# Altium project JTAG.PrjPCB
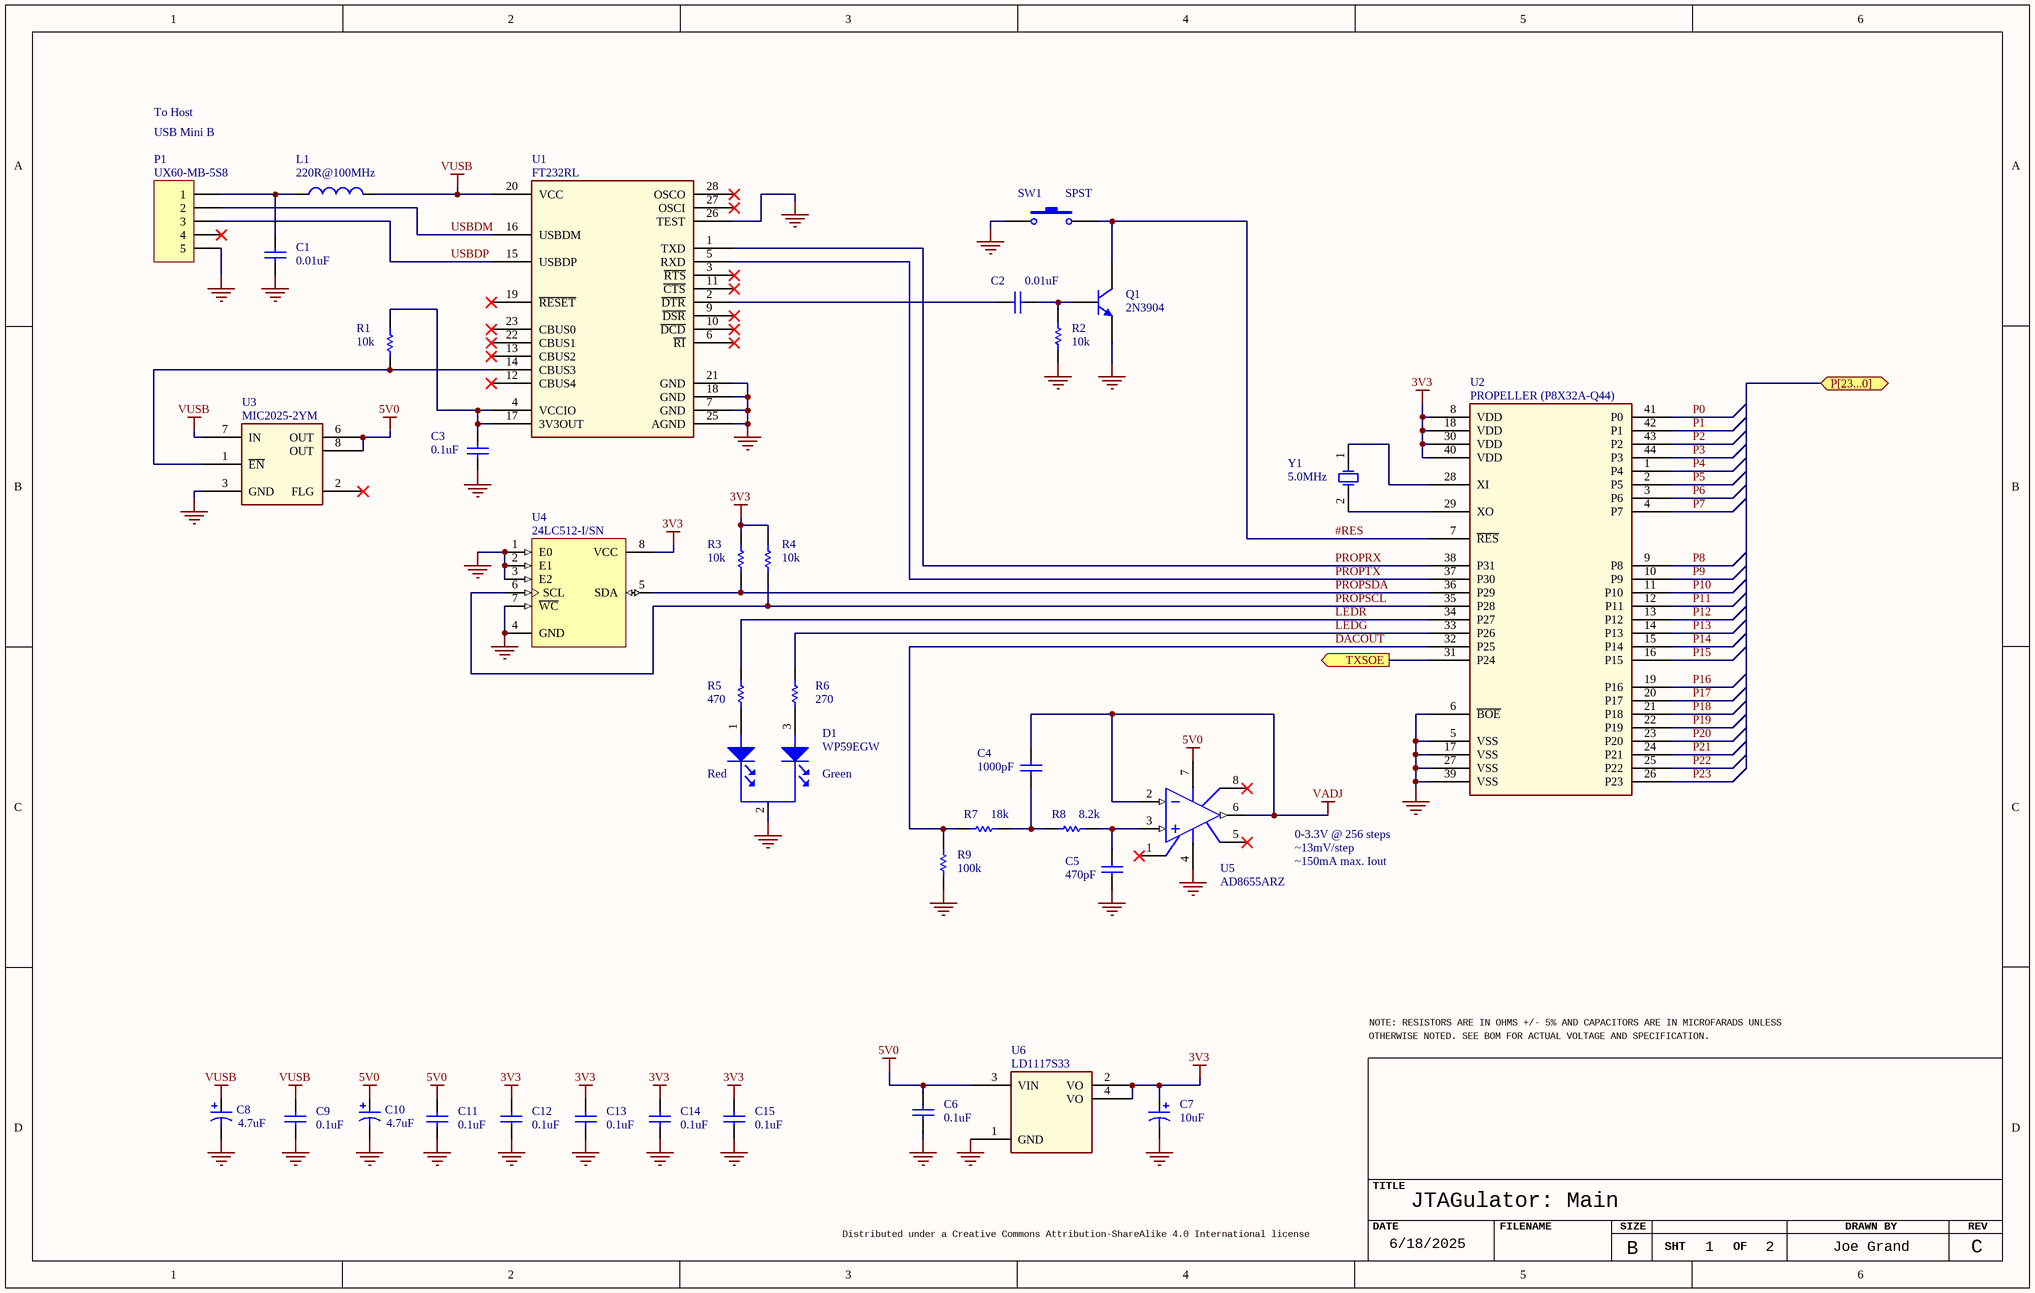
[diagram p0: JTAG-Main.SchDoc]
2 sheets, 65 parts. Net scope: global (net labels, ports and power ports of the same name join across sheets).
Board file: JTAG.PcbDoc
Sheets:
  JTAG-Main.SchDoc
  JTAG-Target.SchDoc

## Sheet JTAG-Main.SchDoc: JTAGulator: Main
size B; Engineer: Joe Grand; Revision: C; SheetNumber: 1; SheetTotal: 2; PageSetup: Record=PageOptions¦CenterHorizontal=True¦CenterVertical=True¦PrintScale=0.70¦XCorrection=1.00¦YCorrection=1.00¦PrintKind=0¦BorderSize=5000000¦LeftOffset=0¦BottomOffset=0¦Orientation=2¦PaperLength=1000¦PaperWidth=1000¦Scale=100¦PaperSource=7¦PrintQuality=-4¦MediaType=1¦DitherType=10¦PaperKind=Letter¦PrintScaleMode=1

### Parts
(Parts that share a designator on the sheet are numbered #1, #2 ... from top to bottom, then left to right.)
*#1  Schematic Modify Date: 6/18/2025  Page Size: B  RevCode: C  Page Count: 2  Page Number: 1  OrgName: Joe Grand  Title: JTAGulator: Main  (hidden comment: GIS Title Block)  (graphical)
C1  value 0.01uF  [C1206]  (hidden comment: Cap)
C2  value 0.01uF  [C1206]  (hidden comment: Cap)
C3  value 0.1uF  [C1206]  (hidden comment: Cap)
C4  value 1000pF  [C1206]  (hidden comment: Cap)
C5  value 470pF  [C1206]  (hidden comment: Cap)
C6  value 0.1uF  [C1206]  (hidden comment: Cap)
C7  value 10uF  [TC3216 (A)]  (hidden comment: Cap Pol1)
C8  value 4.7uF  [TC3216 (A)]  (hidden comment: Cap Pol1)
C9  value 0.1uF  [C1206]  (hidden comment: Cap)
C10  value 4.7uF  [TC3216 (A)]  (hidden comment: Cap Pol1)
C11  value 0.1uF  [C1206]  (hidden comment: Cap)
C12  value 0.1uF  [C1206]  (hidden comment: Cap)
C13  value 0.1uF  [C1206]  (hidden comment: Cap)
C14  value 0.1uF  [C1206]  (hidden comment: Cap)
C15  value 0.1uF  [C1206]  (hidden comment: Cap)
D1  WP59EGW  [WP59EGW]
L1  value 220R@100MHz  [C0805]  (hidden comment: Inductor)
P1  UX60-MB-5S8  [HRS UX60-MB-5S8 MINI-USB - NO SLOTS]
Q1  2N3904  [SOT23-3]
R1  value 10k  [C1206]  (hidden comment: Res1)
R2  value 10k  [C1206]  (hidden comment: Res1)
R3  value 10k  [C1206]  (hidden comment: Res1)
R4  value 10k  [C1206]  (hidden comment: Res1)
R5  value 470  [C1206]  (hidden comment: Res1)
R6  value 270  [C1206]  (hidden comment: Res1)
R7  value 18k  [C1206]  (hidden comment: Res1)
R8  value 8.2k  [C1206]  (hidden comment: Res1)
R9  value 100k  [C1206]  (hidden comment: Res1)
SW1  SPST  [C&K KSC SPST SWITCH]
U1  FT232RL  [SOP65P780-28BN]
U2  PROPELLER (P8X32A-Q44)  [TQFP80P1200X1200-44AN]
U3  MIC2025-2YM  [SOIC127P600-8BM]
U4  24LC512-I/SN  [SOIC127P600-8BM]
U5  AD8655ARZ  [R-8_N]
U6  LD1117S33  [SOT-223]
Y1  5.0MHz  [XTL_HC49-4H]

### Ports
P[23...0] (bidir), TXSOE (out)

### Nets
3V3: C7.1 C12.2 C13.2 C14.2 C15.2 R3.2 R4.2 U2.8(VDD) U2.18(VDD) U2.30(VDD) U2.40(VDD) U4.8(VCC) U6.2(VO) U6.4(VO)
5V0: C6.2 C10.1 C11.2 U3.6(OUT) U3.8(OUT) U5.7(V+) U6.3(VIN)
GND: C1.1 C3.1 C5.1 C6.1 C7.2 C8.2 C9.1 C10.2 C11.1 C12.1 C13.1 C14.1 C15.1 D1.2(CATHODE) P1.5 Q1.1(E) R2.1 R9.1 SW1.2 U1.7(GND) U1.18(GND) U1.21(GND) U1.25(AGND) U1.26(TEST) U2.5(VSS) U2.6(~{BOE}) U2.17(VSS) U2.27(VSS) U2.39(VSS) U3.3(GND) U4.1(E0) U4.2(E1) U4.3(E2) U4.4(GND) U4.7(~{WC}) U5.4(V-) U6.1(GND)
VADJ: C4.2 U5.2(IN-) U5.6(OUT)
VUSB: C8.1 C9.2 L1.2 U1.20(VCC) U3.7(IN)
#RES: Q1.3(C) SW1.1 U2.7(~{RES})
DACOUT: R7.2 R9.2 U2.32(P25)
LEDG: R6.2 U2.33(P26)
LEDR: R5.2 U2.34(P27)
P0: U2.41(P0)
P1: U2.42(P1)
P2: U2.43(P2)
P3: U2.44(P3)
P4: U2.1(P4)
P5: U2.2(P5)
P6: U2.3(P6)
P7: U2.4(P7)
P8: U2.9(P8)
P9: U2.10(P9)
P10: U2.11(P10)
P11: U2.12(P11)
P12: U2.13(P12)
P13: U2.14(P13)
P14: U2.15(P14)
P15: U2.16(P15)
P16: U2.19(P16)
P17: U2.20(P17)
P18: U2.21(P18)
P19: U2.22(P19)
P20: U2.23(P20)
P21: U2.24(P21)
P22: U2.25(P22)
P23: U2.26(P23)
PROPRX: U1.1(TXD) U2.38(P31)
PROPSCL: R4.1 U2.35(P28) U4.6(SCL)
PROPSDA: R3.1 U2.36(P29) U4.5(SDA)
PROPTX: U1.5(RXD) U2.37(P30)
USBDM: P1.2 U1.16(USBDM)
USBDP: P1.3 U1.15(USBDP)
NetC1_2: C1.2 L1.1 P1.1
NetC2_1: C2.1 Q1.2(B) R2.2
NetC2_2: C2.2 U1.2(~{DTR})
NetC3_2: C3.2 R1.2 U1.4(VCCIO) U1.17(3V3OUT)
NetC4_1: C4.1 R7.1 R8.2
NetC5_2: C5.2 R8.1 U5.3(IN+)
NetD1_1: D1.1(ARED) R5.1
NetD1_3: D1.3(AGREEN) R6.1
NetR1_1: R1.1 U1.14(CBUS3) U3.1(~{EN})
NetR10_2: U2.31(P24) ; port TXSOE
NetU2_28: U2.28(XI) Y1.1(OSC1)
NetU2_29: U2.29(XO) Y1.2(OSC2)

Not connected (* = marked no-connect by the designer): P1 4*; U1 3(~{RTS})* 6(~{RI})* 9(~{DSR})* 10(~{DCD})* 11(~{CTS})* 12(CBUS4)* 13(CBUS2)* 19(~{RESET})* 22(CBUS1)* 23(CBUS0)* 27(OSCI)* 28(OSCO)*; U3 2(FLG)*; U5 1(OS_NULL)* 5(OS_NULL)* 8(NC)*

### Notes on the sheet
- To Host
- USB Mini B
- (near D1) Red
- (near D1) Green
- 0-3.3V @ 256 steps
- 3mV/step
- 50mA max. Iout
- (near *#1) OTHERWISE NOTED. SEE BOM FOR ACTUAL VOLTAGE AND SPECIFICATION.
- (near *#1) NOTE: RESISTORS ARE IN OHMS +/- 5% AND CAPACITORS ARE IN MICROFARADS UNLESS
- Distributed under a Creative Commons Attribution-ShareAlike 4.0 International license

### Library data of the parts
C1-C6 C9 C11-C15 = Cap: Capacitor
C7 C8 C10 = Cap Pol1: Polarized Capacitor (Radial)
D1 = SSL-LX5097
L1 = Inductor: MPZ2012S221A
P1 = Header 5: Header, 5-Pin
Q1 = 2N3904: NPN General Purpose Amplifier
R1-R9 = Res1: Resistor
SW1 = SW-PB: Switch
U1 = FT232RL: USB UART Asynchronous Serial Data Transfer Chip
U2 = PROPELLER (ALT)
U3 = MIC2025-2: Single-Channel Power Distribution Switch
U4 = M24C02WDW6: 2Kbit Serial I²C Bus EEPROM
U5 = AD548AR: Low-Noise, Precision CMOS Op Amp; Note: Pin 8 is not connected.
U6 = LD1117: LD1117xx 800mA LDO Linear Regulator
Y1 = XTAL: Crystal Oscillator

## Sheet JTAG-Target.SchDoc: JTAGulator: Target Interface
size B; Engineer: Joe Grand; Revision: C; SheetNumber: 2; SheetTotal: 2; PageSetup: Record=PageOptions¦CenterHorizontal=True¦CenterVertical=True¦PrintScale=0.70¦XCorrection=1.00¦YCorrection=1.00¦PrintKind=0¦BorderSize=5000000¦LeftOffset=0¦BottomOffset=0¦Orientation=2¦PaperLength=1000¦PaperWidth=1000¦Scale=100¦PaperSource=7¦PrintQuality=-4¦MediaType=1¦DitherType=10¦PaperKind=Letter¦PrintScaleMode=1
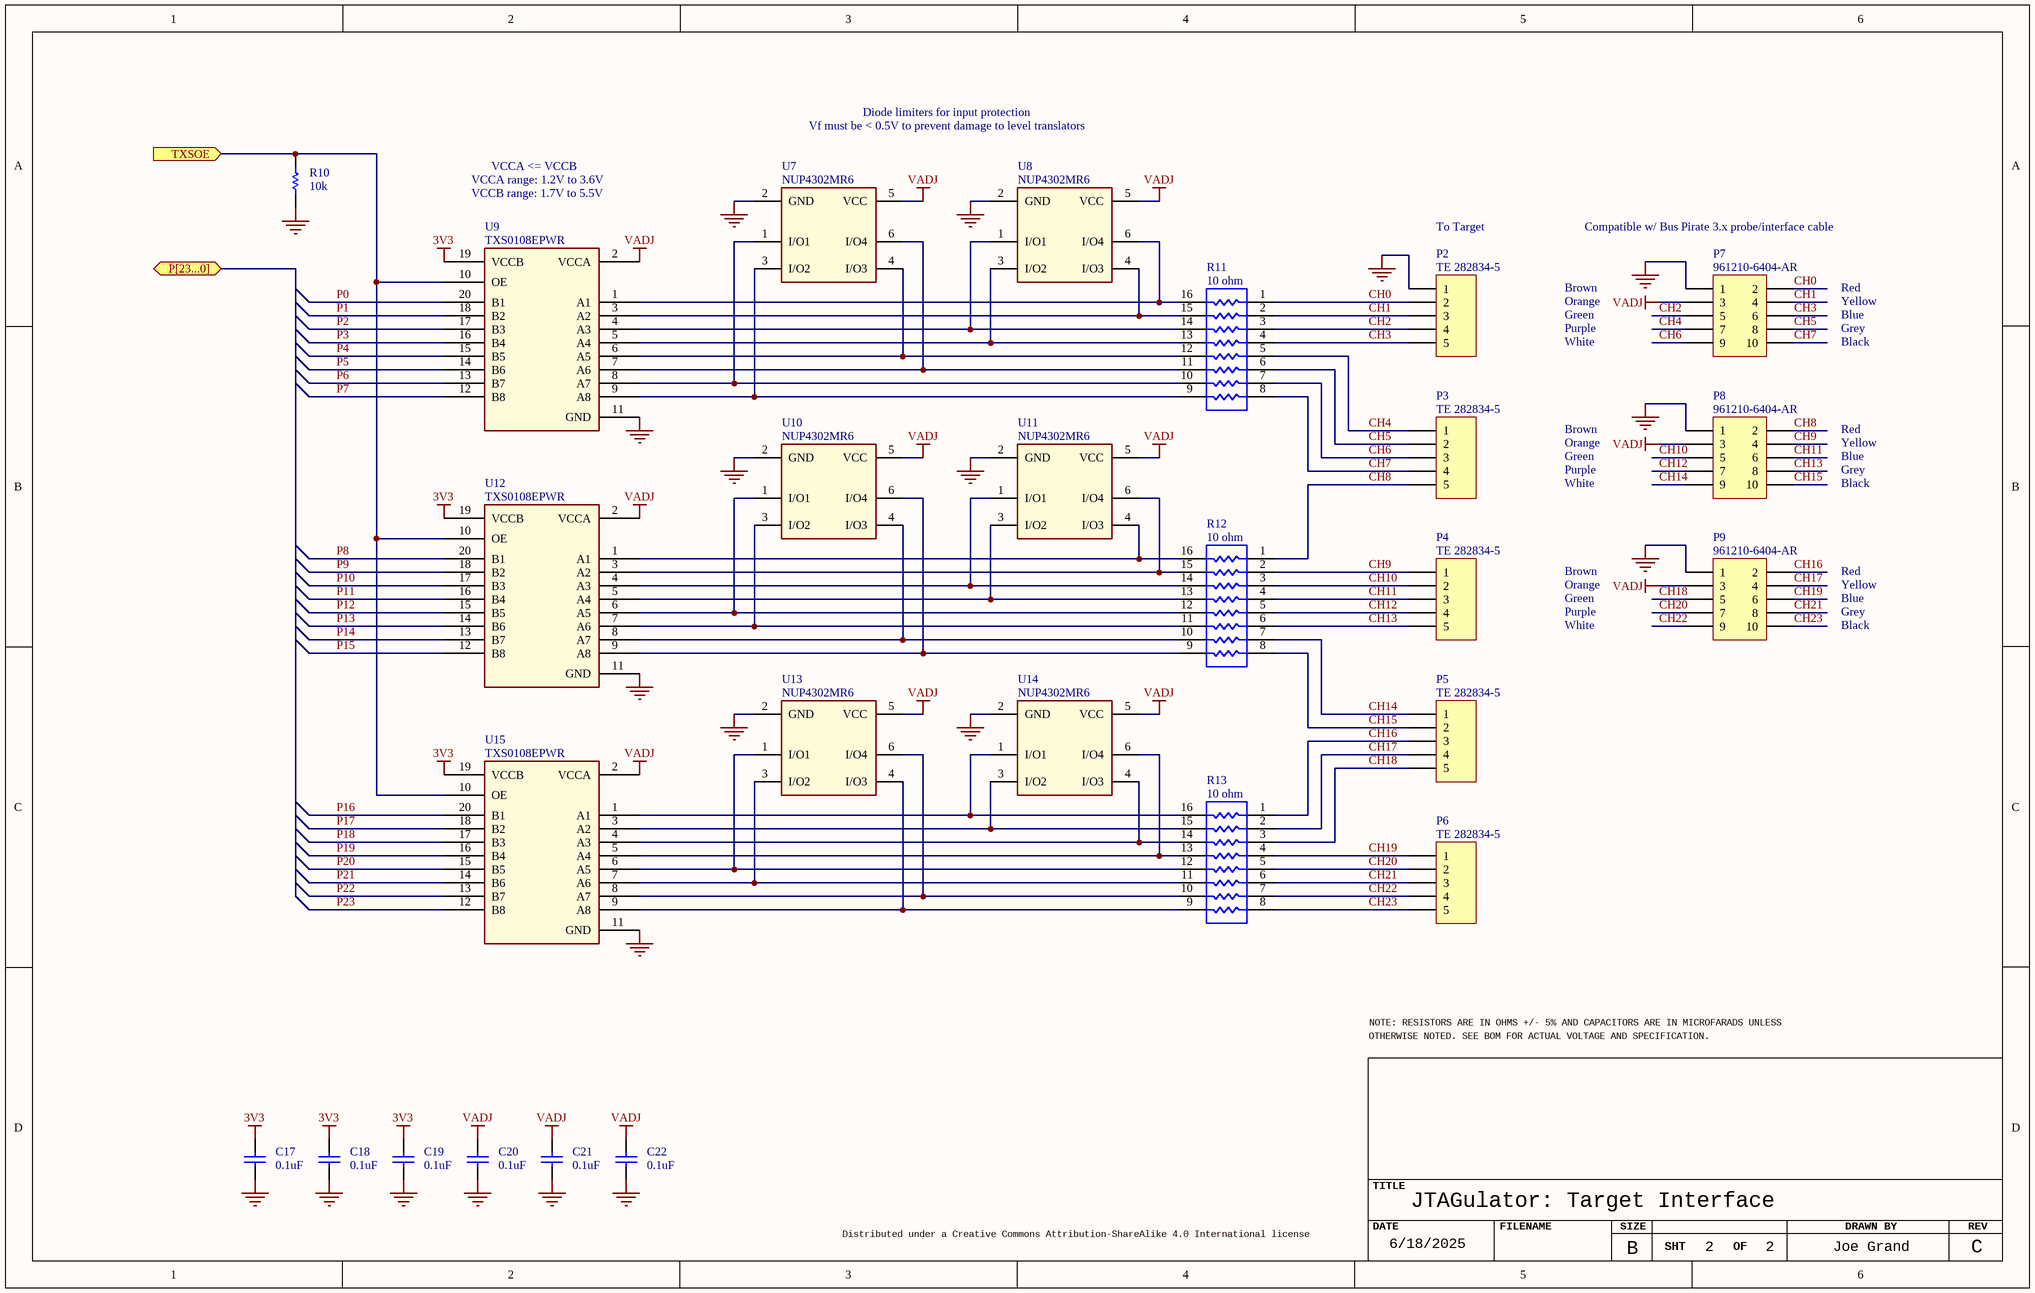
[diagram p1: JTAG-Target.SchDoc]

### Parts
(Parts that share a designator on the sheet are numbered #1, #2 ... from top to bottom, then left to right.)
*#2  Schematic Modify Date: 6/18/2025  Page Size: B  RevCode: C  Page Count: 2  OrgName: Joe Grand  Title: JTAGulator: Target Interface  (hidden comment: GIS Title Block)  (graphical)
C17  value 0.1uF  [C1206]  (hidden comment: Cap)
C18  value 0.1uF  [C1206]  (hidden comment: Cap)
C19  value 0.1uF  [C1206]  (hidden comment: Cap)
C20  value 0.1uF  [C1206]  (hidden comment: Cap)
C21  value 0.1uF  [C1206]  (hidden comment: Cap)
C22  value 0.1uF  [C1206]  (hidden comment: Cap)
P2  TE 282834-5  [TE282834-5]
P3  TE 282834-5  [TE282834-5]
P4  TE 282834-5  [TE282834-5]
P5  TE 282834-5  [TE282834-5]
P6  TE 282834-5  [TE282834-5]
P7  961210-6404-AR  [HDR2X5 - SHROUD]
P8  961210-6404-AR  [HDR2X5 - SHROUD]
P9  961210-6404-AR  [HDR2X5 - SHROUD]
R10  value 10k  [C1206]  (hidden comment: Res1)
R11  value 10 ohm  [SO-G16 - WIDE]  (hidden comment: 4816P-1-102LF)
R12  value 10 ohm  [SO-G16 - WIDE]  (hidden comment: 4816P-1-102LF)
R13  value 10 ohm  [SO-G16 - WIDE]  (hidden comment: 4816P-1-102LF)
U7  NUP4302MR6  [TSOP-6_M]
U8  NUP4302MR6  [TSOP-6_M]
U9  TXS0108EPWR  [SOP65P640-20AN]
U10  NUP4302MR6  [TSOP-6_M]
U11  NUP4302MR6  [TSOP-6_M]
U12  TXS0108EPWR  [SOP65P640-20AN]
U13  NUP4302MR6  [TSOP-6_M]
U14  NUP4302MR6  [TSOP-6_M]
U15  TXS0108EPWR  [SOP65P640-20AN]

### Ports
P[23...0] (bidir), TXSOE (in)

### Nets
3V3: C17.2 C18.2 C19.2 U9.19(VCCB) U12.19(VCCB) U15.19(VCCB)
GND: C17.1 C18.1 C19.1 C20.1 C21.1 C22.1 P2.1 P7.1 P8.1 P9.1 R10.1 U7.2(GND) U8.2(GND) U9.11(GND) U10.2(GND) U11.2(GND) U12.11(GND) U13.2(GND) U14.2(GND) U15.11(GND)
VADJ: C20.2 C21.2 C22.2 P7.3 P8.3 P9.3 U7.5(VCC) U8.5(VCC) U9.2(VCCA) U10.5(VCC) U11.5(VCC) U12.2(VCCA) U13.5(VCC) U14.5(VCC) U15.2(VCCA)
CH0: P2.2 P7.2 R11.1
CH1: P2.3 P7.4 R11.2
CH2: P2.4 P7.5 R11.3
CH3: P2.5 P7.6 R11.4
CH4: P3.1 P7.7 R11.5
CH5: P3.2 P7.8 R11.6
CH6: P3.3 P7.9 R11.7
CH7: P3.4 P7.10 R11.8
CH8: P3.5 P8.2 R12.1
CH9: P4.1 P8.4 R12.2
CH10: P4.2 P8.5 R12.3
CH11: P4.3 P8.6 R12.4
CH12: P4.4 P8.7 R12.5
CH13: P4.5 P8.8 R12.6
CH14: P5.1 P8.9 R12.7
CH15: P5.2 P8.10 R12.8
CH16: P5.3 P9.2 R13.1
CH17: P5.4 P9.4 R13.2
CH18: P5.5 P9.5 R13.3
CH19: P6.1 P9.6 R13.4
CH20: P6.2 P9.7 R13.5
CH21: P6.3 P9.8 R13.6
CH22: P6.4 P9.9 R13.7
CH23: P6.5 P9.10 R13.8
P0: U9.20(B1)
P1: U9.18(B2)
P2: U9.17(B3)
P3: U9.16(B4)
P4: U9.15(B5)
P5: U9.14(B6)
P6: U9.13(B7)
P7: U9.12(B8)
P8: U12.20(B1)
P9: U12.18(B2)
P10: U12.17(B3)
P11: U12.16(B4)
P12: U12.15(B5)
P13: U12.14(B6)
P14: U12.13(B7)
P15: U12.12(B8)
P16: U15.20(B1)
P17: U15.18(B2)
P18: U15.17(B3)
P19: U15.16(B4)
P20: U15.15(B5)
P21: U15.14(B6)
P22: U15.13(B7)
P23: U15.12(B8)
NetR10_2: R10.2 U9.10(OE) U12.10(OE) U15.10(OE) ; port TXSOE
NetR11_9: R11.9 U7.3(I/O2) U9.9(A8)
NetR11_10: R11.10 U7.1(I/O1) U9.8(A7)
NetR11_11: R11.11 U7.6(I/O4) U9.7(A6)
NetR11_12: R11.12 U7.4(I/O3) U9.6(A5)
NetR11_13: R11.13 U8.3(I/O2) U9.5(A4)
NetR11_14: R11.14 U8.1(I/O1) U9.4(A3)
NetR11_15: R11.15 U8.4(I/O3) U9.3(A2)
NetR11_16: R11.16 U8.6(I/O4) U9.1(A1)
NetR12_9: R12.9 U10.6(I/O4) U12.9(A8)
NetR12_10: R12.10 U10.4(I/O3) U12.8(A7)
NetR12_11: R12.11 U10.3(I/O2) U12.7(A6)
NetR12_12: R12.12 U10.1(I/O1) U12.6(A5)
NetR12_13: R12.13 U11.3(I/O2) U12.5(A4)
NetR12_14: R12.14 U11.1(I/O1) U12.4(A3)
NetR12_15: R12.15 U11.6(I/O4) U12.3(A2)
NetR12_16: R12.16 U11.4(I/O3) U12.1(A1)
NetR13_9: R13.9 U13.4(I/O3) U15.9(A8)
NetR13_10: R13.10 U13.6(I/O4) U15.8(A7)
NetR13_11: R13.11 U13.3(I/O2) U15.7(A6)
NetR13_12: R13.12 U13.1(I/O1) U15.6(A5)
NetR13_13: R13.13 U14.6(I/O4) U15.5(A4)
NetR13_14: R13.14 U14.4(I/O3) U15.4(A3)
NetR13_15: R13.15 U14.3(I/O2) U15.3(A2)
NetR13_16: R13.16 U14.1(I/O1) U15.1(A1)

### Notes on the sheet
- Vf must be < 0.5V to prevent damage to level translators
- Diode limiters for input protection
- VCCA range: 1.2V to 3.6V
- VCCB range: 1.7V to 5.5V
- VCCA <= VCCB
- To Target
- Compatible w/ Bus Pirate 3.x probe/interface cable
- Brown
- Red
- Orange
- Green
- Purple
- White
- Yellow
- Blue
- Grey
- Black
- (near *#2) OTHERWISE NOTED. SEE BOM FOR ACTUAL VOLTAGE AND SPECIFICATION.
- (near *#2) NOTE: RESISTORS ARE IN OHMS +/- 5% AND CAPACITORS ARE IN MICROFARADS UNLESS
- Distributed under a Creative Commons Attribution-ShareAlike 4.0 International license

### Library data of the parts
C17-C22 = Cap: Capacitor
P2-P6 = Header 5: Header, 5-Pin
P7-P9 = Header 5X2: Header, 5-Pin, Dual row; Shrouded Version: Molex 90130-1110
R10 = Res1: Resistor
R11-R13 = Res Pack3: Isolated Resistor Network
U7 U8 U10 U11 U13 U14 = NUP4302MR6: IC Schottky Diode Array TSOP-6

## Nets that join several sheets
3V3: JTAG-Main (14 pins), JTAG-Target (6 pins)
GND: JTAG-Main (37 pins), JTAG-Target (20 pins)
VADJ: JTAG-Main (C4.2 U5.2 U5.6), JTAG-Target (15 pins)
NetR10_2: JTAG-Main (U2.31), JTAG-Target (R10.2 U9.10 U12.10 U15.10)
P0: JTAG-Main (U2.41), JTAG-Target (U9.20)
P1: JTAG-Main (U2.42), JTAG-Target (U9.18)
P2: JTAG-Main (U2.43), JTAG-Target (U9.17)
P3: JTAG-Main (U2.44), JTAG-Target (U9.16)
P4: JTAG-Main (U2.1), JTAG-Target (U9.15)
P5: JTAG-Main (U2.2), JTAG-Target (U9.14)
P6: JTAG-Main (U2.3), JTAG-Target (U9.13)
P7: JTAG-Main (U2.4), JTAG-Target (U9.12)
P8: JTAG-Main (U2.9), JTAG-Target (U12.20)
P9: JTAG-Main (U2.10), JTAG-Target (U12.18)
P10: JTAG-Main (U2.11), JTAG-Target (U12.17)
P11: JTAG-Main (U2.12), JTAG-Target (U12.16)
P12: JTAG-Main (U2.13), JTAG-Target (U12.15)
P13: JTAG-Main (U2.14), JTAG-Target (U12.14)
P14: JTAG-Main (U2.15), JTAG-Target (U12.13)
P15: JTAG-Main (U2.16), JTAG-Target (U12.12)
P16: JTAG-Main (U2.19), JTAG-Target (U15.20)
P17: JTAG-Main (U2.20), JTAG-Target (U15.18)
P18: JTAG-Main (U2.21), JTAG-Target (U15.17)
P19: JTAG-Main (U2.22), JTAG-Target (U15.16)
P20: JTAG-Main (U2.23), JTAG-Target (U15.15)
P21: JTAG-Main (U2.24), JTAG-Target (U15.14)
P22: JTAG-Main (U2.25), JTAG-Target (U15.13)
P23: JTAG-Main (U2.26), JTAG-Target (U15.12)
